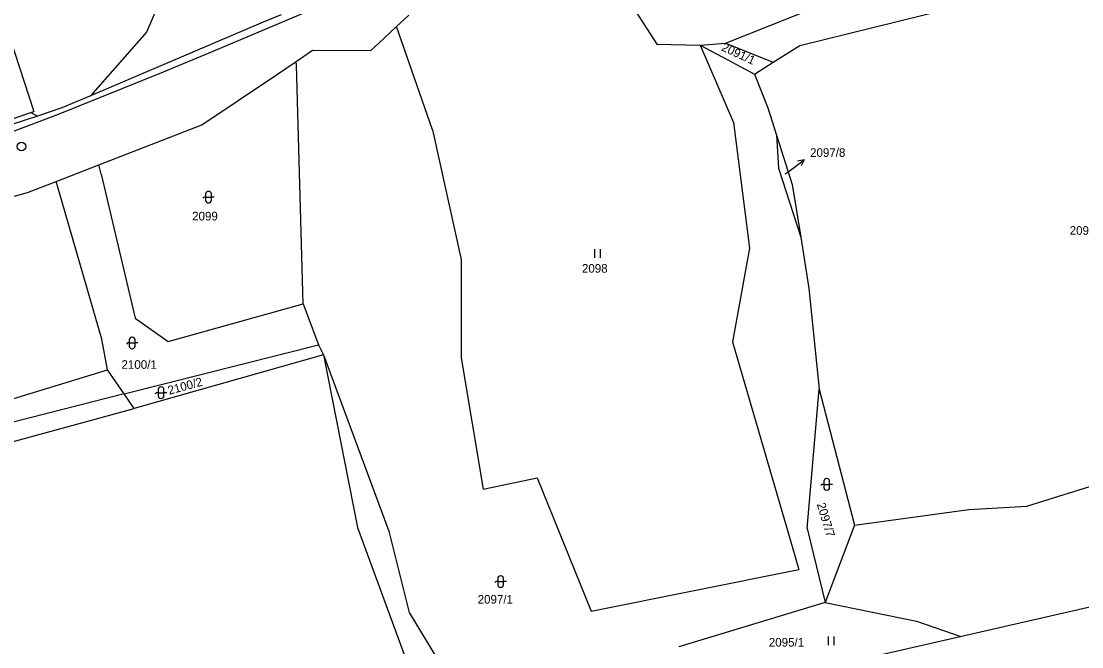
# Model space of a CAD drawing. Extents: x -805730 to -804640, y -1150889 to -1150366.
# Drawn here: x -805108.7 to -804924.5, y -1150727 to -1150618.3 of the extents above; entities that cross this region are included whole.
import ezdxf

# ---------------------------------------------------------------- set-up
doc = ezdxf.new("R2010")
doc.units = 0
for name, color, linetype in [('Default', 7, 'Continuous'), ('formát', 7, 'Continuous'), ('kilometráž - vrstava 7', 7, 'Continuous'), ('kn_celek - Cisla parcel pomocna', 7, 'Continuous'), ('kn_celek - Cisla pozemkovych parcel', 7, 'Continuous'), ('kn_celek - Hranice parcel', 7, 'Continuous'), ('kn_celek - Znacky kultur', 7, 'Continuous'), ('plochy - SZDC', 7, 'Continuous'), ('PSR_C2_2_trasa_Vimperk - Kabelová trasa', 7, 'Continuous')]:
    doc.layers.add(name, color=color, linetype=linetype)

# ---------------------------------------------------------------- blocks, each defined once
blk = doc.blocks.new('306')
at = {"layer": 'Default'}
for p, q in [((-5.2, 0), (-5.2, 15)), ((4.8, 0), (4.8, 15))]:
    blk.add_line(p, q, dxfattribs=at)
blk = doc.blocks.new('316')
at = {"layer": 'Default'}
for p, q in [((0.5, 20), (-0.5, 20)), ((-8.3, 10), (-10, 8.1)), ((-5, 10), (-8.3, 10)), ((-5, 15.5), (-5, 4.5)), ((-5, 10), (5, 10)), ((-0.5, 0), (0.5, 0)), ((5, 4.5), (5, 15.5)), ((10, 10), (5, 10))]:
    blk.add_line(p, q, dxfattribs=at)
for centre, start, end in [((-0.5, 15.5), 90, 180), ((0.5, 15.5), 0, 90), ((-0.5, 4.5), 180, 270), ((0.5, 4.5), 270, 0)]:
    blk.add_arc(centre, 4.5, start, end, dxfattribs=at)
blk = doc.blocks.new('Z61')
at = {"layer": 'Default'}
for p, q in [((0, 0), (30, 0)), ((30, 0), (19.2, 5.3)), ((30, 0), (19.2, -5.3))]:
    blk.add_line(p, q, dxfattribs=at)

msp = doc.modelspace()

# ---------------------------------------------------------------- linework, layer by layer
at = {"layer": 'formát'}
msp.add_line((-804845.15, -1150702.29), (-805049.87, -1150749.08), dxfattribs=at)
at = {"layer": 'kilometráž - vrstava 7'}
msp.add_circle((-805108.67, -1150640.09), 0.75, dxfattribs=at)
at = {"layer": 'kn_celek - Cisla parcel pomocna'}
msp.add_line((-804976.06, -1150644.85), (-804975.13, -1150644.17), dxfattribs=at)
at = {"layer": 'kn_celek - Hranice parcel'}
for p, q in [((-804986.38, -1150622.16), (-804942.25, -1150604.51)), ((-805081.28, -1150606.99), (-805086.98, -1150620.2)), ((-804973.51, -1150622.54), (-804938.45, -1150613.86)), ((-805003.05, -1150614.96), (-804998.33, -1150622.28)), ((-805063.58, -1150617.18), (-805066.7, -1150618.51)), ((-805043.51, -1150619.25), (-805041.4, -1150617.28)), ((-805066.7, -1150618.51), (-805096.7, -1150631.27)), ((-805045.75, -1150621.33), (-805043.51, -1150619.25)), ((-805037.3, -1150637.19), (-805043.51, -1150619.25)), ((-805110.75, -1150621.04), (-805106.53, -1150634.03)), ((-805086.98, -1150620.2), (-805096.7, -1150631.27)), ((-805048.02, -1150623.43), (-805045.75, -1150621.33)), ((-804998.33, -1150622.28), (-804990.78, -1150622.47)), ((-804990.78, -1150622.47), (-804986.38, -1150622.16)), ((-804990.78, -1150622.47), (-804984.99, -1150635.89)), ((-804990.78, -1150622.47), (-804986.09, -1150624.98)), ((-804986.38, -1150622.16), (-804978.11, -1150625.46)), ((-804978.11, -1150625.46), (-804973.51, -1150622.54)), ((-805060.95, -1150625.29), (-805058.1, -1150623.37)), ((-805058.1, -1150623.37), (-805048.02, -1150623.43)), ((-804986.09, -1150624.98), (-804981.36, -1150627.52)), ((-805064.56, -1150627.72), (-805060.95, -1150625.29)), ((-805060.93, -1150625.95), (-805060.95, -1150625.29)), ((-805059.81, -1150665.31), (-805060.93, -1150625.95)), ((-804981.36, -1150627.52), (-804978.11, -1150625.46)), ((-805077.33, -1150636.32), (-805064.56, -1150627.72)), ((-804981.36, -1150627.52), (-804979.02, -1150633.36)), ((-805096.7, -1150631.27), (-805101.66, -1150633.38)), ((-805120.75, -1150638.84), (-805107.03, -1150634.2)), ((-805107.03, -1150634.2), (-805106.53, -1150634.03)), ((-805107.03, -1150634.2), (-805105.89, -1150634.79)), ((-805101.66, -1150633.38), (-805105.89, -1150634.79)), ((-804979.02, -1150633.36), (-804977.52, -1150638.12)), ((-805105.89, -1150634.79), (-805128.92, -1150642.38)), ((-804984.99, -1150635.89), (-804982.22, -1150657.75)), ((-805095.21, -1150643.26), (-805077.33, -1150636.32)), ((-805037.3, -1150637.19), (-805032.3, -1150659.73)), ((-804977.52, -1150638.12), (-804974.82, -1150646.67)), ((-804977.52, -1150638.12), (-804977.2, -1150643.87)), ((-805102.65, -1150646.15), (-805095.21, -1150643.26)), ((-805094.83, -1150644.88), (-805095.21, -1150643.26)), ((-805094.83, -1150644.88), (-805088.91, -1150669.91)), ((-804977.2, -1150643.87), (-804973.34, -1150655.86)), ((-805107.63, -1150648.08), (-805102.65, -1150646.15)), ((-805102.25, -1150647.55), (-805102.65, -1150646.15)), ((-804974.82, -1150646.67), (-804973.34, -1150655.86)), ((-805129.38, -1150653.98), (-805107.63, -1150648.08)), ((-805094.73, -1150673.57), (-805102.25, -1150647.55)), ((-804973.34, -1150655.86), (-804971.91, -1150664.74)), ((-804982.22, -1150657.75), (-804985.2, -1150674.05)), ((-805032.3, -1150659.73), (-805032.3, -1150676.79)), ((-805059.75, -1150667.41), (-805059.81, -1150665.31)), ((-804971.91, -1150664.74), (-804970.15, -1150682.23)), ((-805083.21, -1150673.96), (-805059.75, -1150667.41)), ((-805059.75, -1150667.41), (-805057.08, -1150674.52)), ((-805088.91, -1150669.91), (-805083.21, -1150673.96)), ((-805093.75, -1150678.86), (-805094.73, -1150673.57)), ((-805090.83, -1150683.08), (-805057.08, -1150674.52)), ((-805057.08, -1150674.52), (-805056.24, -1150676.26)), ((-804985.2, -1150674.05), (-804975.34, -1150707.8)), ((-805056.24, -1150676.26), (-805089.07, -1150685.63)), ((-805056.24, -1150676.26), (-805050.29, -1150706.27)), ((-805056.24, -1150676.26), (-805044.87, -1150706.91)), ((-805032.3, -1150676.79), (-805028.51, -1150699.61)), ((-805122.34, -1150687.69), (-805093.75, -1150678.86)), ((-805090.83, -1150683.08), (-805093.75, -1150678.86)), ((-805090.83, -1150683.08), (-805126.05, -1150692)), ((-805089.07, -1150685.63), (-805090.83, -1150683.08)), ((-804972.2, -1150706.48), (-804970.15, -1150682.23)), ((-804970.15, -1150682.23), (-804964, -1150705.89)), ((-805118.57, -1150693.67), (-805089.07, -1150685.63)), ((-804934.05, -1150702.55), (-804906.46, -1150693.95)), ((-805028.51, -1150699.61), (-805019.11, -1150697.63)), ((-805019.11, -1150697.63), (-805009.75, -1150720.81)), ((-804964, -1150705.89), (-804944.11, -1150703.14)), ((-804944.11, -1150703.14), (-804934.05, -1150702.55)), ((-804964, -1150705.89), (-804969.06, -1150719.29)), ((-805050.29, -1150706.27), (-805040.7, -1150732.48)), ((-805044.87, -1150706.91), (-805041.32, -1150721.06)), ((-804975.34, -1150707.8), (-804973.65, -1150713.57)), ((-804972.2, -1150706.48), (-804969.06, -1150719.29)), ((-805009.75, -1150720.81), (-804973.65, -1150713.57)), ((-804969.06, -1150719.29), (-804994.48, -1150727.02)), ((-804969.06, -1150719.29), (-804953.22, -1150722.57)), ((-805041.32, -1150721.06), (-805031.98, -1150736.39)), ((-804953.22, -1150722.57), (-804945.55, -1150725.24))]:
    msp.add_line(p, q, dxfattribs=at)
at = {"layer": 'plochy - SZDC'}
for p, q in [((-805063.58, -1150617.18), (-805066.7, -1150618.51)), ((-805043.51, -1150619.25), (-805041.4, -1150617.28)), ((-805066.7, -1150618.51), (-805096.7, -1150631.27)), ((-805045.75, -1150621.33), (-805043.51, -1150619.25)), ((-805048.02, -1150623.43), (-805045.75, -1150621.33)), ((-805060.95, -1150625.29), (-805058.1, -1150623.37)), ((-805058.1, -1150623.37), (-805048.02, -1150623.43)), ((-805064.56, -1150627.72), (-805060.95, -1150625.29)), ((-805077.33, -1150636.32), (-805064.56, -1150627.72)), ((-805096.7, -1150631.27), (-805101.66, -1150633.38)), ((-805101.66, -1150633.38), (-805105.89, -1150634.79)), ((-805105.89, -1150634.79), (-805128.92, -1150642.38)), ((-805095.21, -1150643.26), (-805077.33, -1150636.32)), ((-805102.65, -1150646.15), (-805095.21, -1150643.26)), ((-805107.63, -1150648.08), (-805102.65, -1150646.15)), ((-805129.38, -1150653.98), (-805107.63, -1150648.08))]:
    msp.add_line(p, q, dxfattribs=at)
at = {"layer": 'PSR_C2_2_trasa_Vimperk - Kabelová trasa'}
msp.add_lwpolyline([(-805122.45, -1150641.59), (-805112.53, -1150638.37), (-805102.25, -1150634.46), (-805084.03, -1150627.11), (-805075.4, -1150623.5), (-805060.17, -1150617.08), (-805047.9, -1150611.92), (-805039.79, -1150608.5), (-804989.01, -1150587.76)], dxfattribs=at)

# ---------------------------------------------------------------- block references
at = {"layer": 'kn_celek - Cisla parcel pomocna', "xscale": 0.09999999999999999, "yscale": 0.10000000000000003, "rotation": 36.29079000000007}
msp.add_blockref('Z61', (-804975.13, -1150644.17), dxfattribs=at)
at = {"layer": 'kn_celek - Znacky kultur', "xscale": 0.1, "yscale": 0.10000000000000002}
for name, p in [('316', (-805076.18, -1150649.88)), ('306', (-805008.58, -1150659.41)), ('316', (-805089.45, -1150675.22)), ('316', (-805084.43, -1150683.86)), ('316', (-804968.81, -1150699.79)), ('316', (-805025.45, -1150716.67)), ('306', (-804968, -1150726.71))]:
    msp.add_blockref(name, p, dxfattribs=at)

# ---------------------------------------------------------------- texts
at = {"layer": 'kn_celek - Cisla parcel pomocna'}
msp.add_text('2097/8', height=1.5, dxfattribs=at).set_placement((-804971.71, -1150641.89))
at = {"layer": 'kn_celek - Cisla pozemkovych parcel'}
for s, rotation, p in [('2091/1', 335.2072, (-804987.22, -1150623.35)), ('2100/2', 15.3, (-805083.02, -1150683.23)), ('2097/7', 286.6661, (-804970.55, -1150702.22))]:
    msp.add_text(s, height=1.5, rotation=rotation, dxfattribs=at).set_placement(p)
for s, height, p in [('2097/8', 0.1, (-804976.34, -1150644.82)), ('2099', 1.5, (-805079.03, -1150652.93)), ('2092', 1.5, (-804926.62, -1150655.42)), ('2098', 1.5, (-805011.33, -1150662.01)), ('2100/1', 1.5, (-805091.3, -1150678.71)), ('2097/1', 1.5, (-805029.44, -1150719.51)), ('2095/1', 1.5, (-804978.87, -1150726.97))]:
    msp.add_text(s, height=height, dxfattribs=at).set_placement(p)

doc.saveas('drawing.dxf')
